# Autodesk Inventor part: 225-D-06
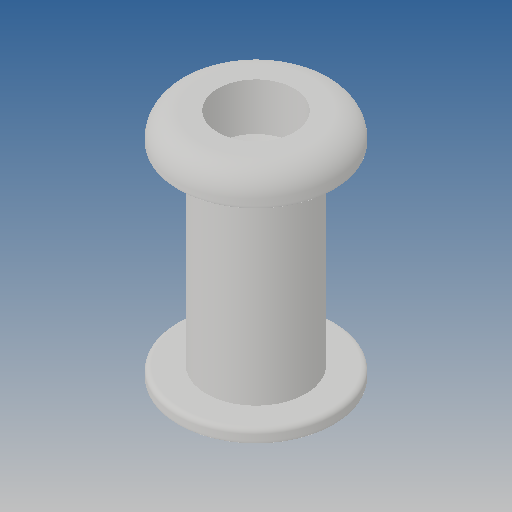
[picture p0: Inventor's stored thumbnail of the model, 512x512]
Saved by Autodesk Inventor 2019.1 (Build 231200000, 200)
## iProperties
Created: 2015-08
Part Number: 225-D-06
Material: Ogólny
Document SubType Name: Modeling
Designer: CADENGINEERING4
Density: 1 g/cm^3
Appearance: Domyślna
Author: CADENGINEERING4
Revision Number: ÈÎºÎ
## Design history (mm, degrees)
feature "Ðý×ª1"
node "Bryła1"
